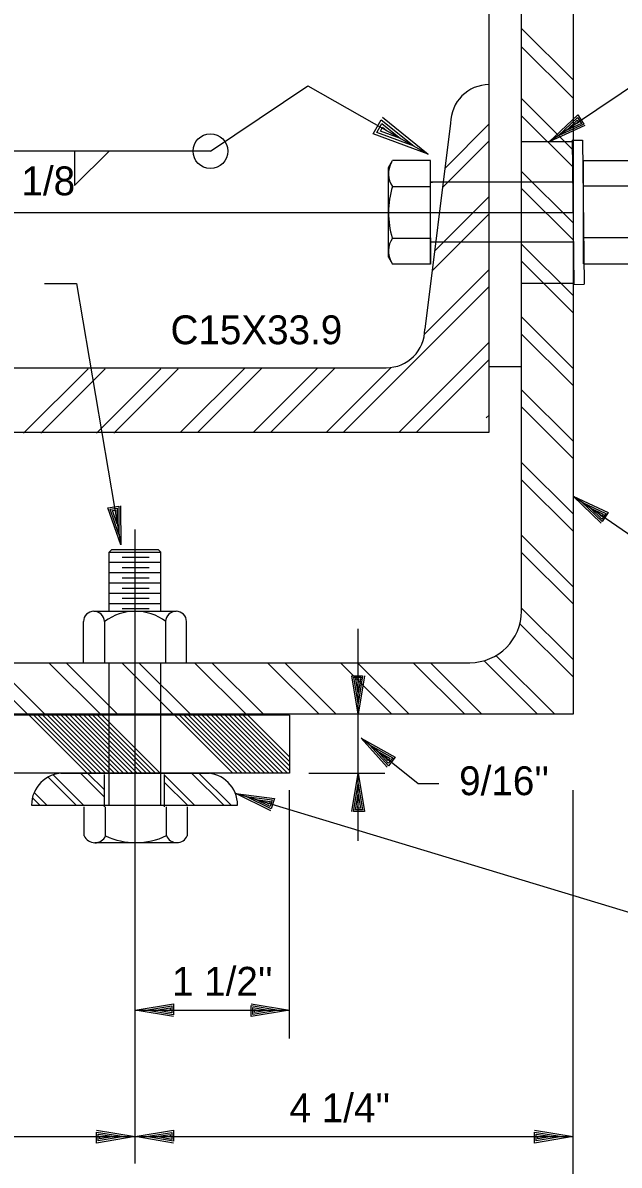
# Model space of a CAD drawing. Extents: x 0.1 to 13.5, y 0.1 to 9.5.
# Drawn here: x 5.352 to 6.316, y 1.255 to 3.105 of the extents above; entities that cross this region are included whole.
import ezdxf

# ---------------------------------------------------------------- set-up
doc = ezdxf.new("R2010")
doc.units = 0
for name, color, linetype in [('Level 1', 7, 'Continuous'), ('Level 10', 7, 'Continuous'), ('Level 13', 7, 'Continuous'), ('Level 2', 7, 'Continuous'), ('Level 25', 7, 'Continuous'), ('Level 3', 7, 'Continuous'), ('Level 36', 7, 'Continuous'), ('Level 50', 7, 'Continuous')]:
    doc.layers.add(name, color=color, linetype=linetype)

msp = doc.modelspace()

# ---------------------------------------------------------------- linework, layer by layer
at = {"layer": 'Level 1'}
msp.add_line((5.4129, 1.8899), (5.6536, 1.8899), dxfattribs=at)
for centre, start, end in [((5.4178, 1.8378), 90, 180), ((5.6469, 1.8378), 0, 90)]:
    msp.add_arc(centre, 0.0521, start, end, dxfattribs=at)
at = {"layer": 'Level 10'}
for p, q in [((5.4496, 1.8378), (5.4005, 1.8869)), ((5.4839, 1.8507), (5.4447, 1.8899)), ((5.4839, 1.8625), (5.4564, 1.8899)), ((5.6295, 1.8378), (5.5809, 1.8864)), ((5.6767, 1.8378), (5.6246, 1.8899)), ((5.6884, 1.8378), (5.6364, 1.8899)), ((5.4378, 1.8378), (5.3924, 1.8833)), ((5.6177, 1.8378), (5.5809, 1.8747)), ((5.3789, 1.8378), (5.3671, 1.8497)), ((5.3907, 1.8378), (5.37, 1.8585))]:
    msp.add_line(p, q, dxfattribs=at)
at = {"layer": 'Level 13'}
for p, q in [((6.2403, 2.9144), (6.257, 2.9145)), ((6.2403, 2.9144), (6.2426, 2.681)), ((6.257, 2.9145), (6.2593, 2.6812)), ((5.9431, 2.8702), (5.9496, 2.8814)), ((5.9431, 2.7252), (5.9431, 2.8702)), ((6.011, 2.8814), (5.9496, 2.8814)), ((6.011, 2.7139), (6.011, 2.8814)), ((6.2585, 2.7145), (6.2585, 2.8819)), ((6.2585, 2.8819), (6.338, 2.8819)), ((5.9494, 2.8397), (6.011, 2.8397)), ((6.2414, 2.8467), (6.011, 2.8467)), ((6.014, 2.8462), (6.011, 2.8462)), ((6.3382, 2.8402), (6.2585, 2.8402)), ((5.9494, 2.7557), (6.011, 2.7557)), ((6.011, 2.7563), (6.011, 2.7139)), ((6.3382, 2.7563), (6.2585, 2.7563)), ((6.2414, 2.7497), (6.011, 2.7497)), ((6.014, 2.7492), (6.011, 2.7492)), ((5.9431, 2.7252), (5.9496, 2.7139)), ((6.011, 2.7139), (5.9496, 2.7139)), ((6.2585, 2.7145), (6.338, 2.7145)), ((6.2426, 2.681), (6.2593, 2.6812)), ((5.4914, 2.2476), (5.4958, 2.2519)), ((5.4914, 2.2478), (5.5747, 2.2478)), ((5.4914, 2.1518), (5.4914, 2.2476)), ((5.4958, 2.2519), (5.5705, 2.2519)), ((5.5123, 2.2395), (5.5559, 2.2395)), ((5.5747, 2.2473), (5.5705, 2.2519)), ((5.5747, 2.1518), (5.5747, 2.2473)), ((5.4914, 2.2311), (5.5747, 2.2311)), ((5.5123, 2.2228), (5.5559, 2.2228)), ((5.4914, 2.2145), (5.5747, 2.2145)), ((5.5123, 2.2061), (5.5559, 2.2061)), ((5.4914, 2.1978), (5.5747, 2.1978)), ((5.5123, 2.1895), (5.5559, 2.1895)), ((5.4914, 2.1811), (5.5747, 2.1811)), ((5.4914, 2.1645), (5.5747, 2.1645)), ((5.5123, 2.1728), (5.5559, 2.1728)), ((5.4667, 2.1518), (5.5996, 2.1518)), ((5.5123, 2.1561), (5.5559, 2.1561)), ((5.4497, 2.0686), (5.4497, 2.1351)), ((5.4842, 2.0686), (5.4842, 2.1351)), ((5.5827, 2.0686), (5.5827, 2.1351)), ((5.6164, 2.0686), (5.6164, 2.1351)), ((5.7831, 1.9837), (4.8892, 1.9837)), ((5.362, 1.9837), (5.4557, 1.8899)), ((5.3694, 1.9837), (5.4631, 1.8899)), ((5.3767, 1.9837), (5.4705, 1.8899)), ((5.3841, 1.9837), (5.4779, 1.8899)), ((5.3914, 1.9837), (5.4852, 1.8899)), ((5.3988, 1.9837), (5.4926, 1.8899)), ((5.4062, 1.9837), (5.4999, 1.8899)), ((5.4136, 1.9837), (5.5073, 1.8899)), ((5.4209, 1.9837), (5.5147, 1.8899)), ((5.4283, 1.9837), (5.522, 1.8899)), ((5.4357, 1.9837), (5.5294, 1.8899)), ((5.443, 1.9837), (5.5368, 1.8899)), ((5.4504, 1.9837), (5.5441, 1.8899)), ((5.4577, 1.9837), (5.5515, 1.8899)), ((5.4651, 1.9837), (5.5589, 1.8899)), ((5.4725, 1.9837), (5.5662, 1.8899)), ((5.4798, 1.9837), (5.5736, 1.8899)), ((5.5977, 1.9837), (5.6914, 1.8899)), ((5.605, 1.9837), (5.6988, 1.8899)), ((5.6124, 1.9837), (5.7062, 1.8899)), ((5.6197, 1.9837), (5.7135, 1.8899)), ((5.6271, 1.9837), (5.7209, 1.8899)), ((5.6345, 1.9837), (5.7282, 1.8899)), ((5.6419, 1.9837), (5.7356, 1.8899)), ((5.6492, 1.9837), (5.7429, 1.8899)), ((5.6566, 1.9837), (5.7503, 1.8899)), ((5.6639, 1.9837), (5.7577, 1.8899)), ((5.6713, 1.9837), (5.7651, 1.8899)), ((5.6787, 1.9837), (5.7724, 1.8899)), ((5.686, 1.9837), (5.7798, 1.8899)), ((5.6934, 1.9837), (5.7831, 1.894)), ((5.7008, 1.9837), (5.7831, 1.9014)), ((5.7082, 1.9837), (5.7831, 1.9087)), ((5.7155, 1.9837), (5.7831, 1.9161)), ((5.7831, 1.9837), (5.7831, 1.8899)), ((5.7831, 1.8899), (5.0871, 1.8899)), ((5.451, 1.8899), (5.6177, 1.8899)), ((5.451, 1.7884), (5.451, 1.8354)), ((5.4854, 1.788), (5.4854, 1.8354)), ((5.584, 1.7882), (5.584, 1.8354)), ((5.6177, 1.7884), (5.6177, 1.8354)), ((5.468, 1.7772), (5.6009, 1.7772))]:
    msp.add_line(p, q, dxfattribs=at)
for centre, radius, start, end in [((5.9794, 2.8602), 0.0364, 149.7124, 214.511), ((6.0886, 2.7972), 0.1455, 163.0184, 196.4966), ((5.9794, 2.7352), 0.0364, 145.489, 210.2876), ((5.4666, 2.1349), 0.0169, 0.5658, 179.4341), ((5.5334, 2.0707), 0.0812, 52.4343, 127.5657), ((5.5995, 2.1349), 0.0169, 0.4975, 179.5025), ((5.4682, 1.7958), 0.0188, 203.1675, 335.9991), ((5.5343, 1.891), 0.1138, 244.5519, 295.884), ((5.6008, 1.7955), 0.0182, 202.375, 337.1995)]:
    msp.add_arc(centre, radius, start, end, dxfattribs=at)
at = {"layer": 'Level 2'}
for p, q in [((5.4914, 1.8378), (5.4914, 2.0686)), ((5.5747, 1.8378), (5.5747, 2.0686)), ((5.4839, 1.8354), (5.4839, 1.8875)), ((5.5809, 1.8354), (5.5809, 1.8875)), ((5.3657, 1.8378), (5.699, 1.8378))]:
    msp.add_line(p, q, dxfattribs=at)
at = {"layer": 'Level 25'}
for p, q in [((6.106, 3.0045), (6.106, 3.8691)), ((6.1581, 2.5481), (6.1581, 3.8692)), ((6.2414, 3.0122), (6.1581, 3.0956)), ((6.2414, 2.9825), (6.1581, 3.0658)), ((5.655, 2.8968), (5.8125, 3.0026)), ((5.8125, 3.0026), (6.0069, 2.8918)), ((6.2414, 2.8986), (6.1581, 2.9819)), ((6.0435, 2.942), (6.0018, 2.6086)), ((6.106, 2.9411), (6.0345, 2.8695)), ((6.2414, 2.8708), (6.1581, 2.9542)), ((5.9843, 2.9047), (5.9843, 2.9047)), ((6.106, 2.9133), (6.0305, 2.8377)), ((6.1581, 2.9123), (6.2414, 2.9123)), ((5.655, 2.8968), (5.2799, 2.8968)), ((5.4354, 2.8973), (5.4354, 2.8411)), ((5.4354, 2.8411), (5.4912, 2.897)), ((6.0069, 2.8918), (6.0069, 2.8918)), ((6.2414, 2.7807), (6.1581, 2.8641)), ((6.2414, 2.753), (6.1581, 2.8363)), ((6.106, 2.8232), (6.0176, 2.7348)), ((4.486, 2.7977), (6.2414, 2.7977)), ((6.106, 2.7954), (6.0136, 2.7031)), ((6.2414, 2.6629), (6.1581, 2.7462)), ((6.106, 2.7053), (6.0008, 2.6001)), ((6.2414, 2.6351), (6.1581, 2.7185)), ((6.1581, 2.6831), (6.2414, 2.6831)), ((6.106, 2.6776), (5.8704, 2.442)), ((6.2414, 2.545), (6.1581, 2.6284)), ((6.2414, 2.5173), (6.1581, 2.6006)), ((6.106, 2.5875), (5.9605, 2.442)), ((6.106, 2.5597), (5.9883, 2.442)), ((4.6416, 2.5461), (5.9393, 2.5461)), ((5.4572, 2.5446), (5.353, 2.4404)), ((5.485, 2.5446), (5.3808, 2.4404)), ((5.5751, 2.5446), (5.4709, 2.4404)), ((5.6028, 2.5446), (5.4987, 2.4404)), ((5.7111, 2.5461), (5.6069, 2.442)), ((5.7389, 2.5461), (5.6347, 2.442)), ((5.829, 2.5461), (5.7248, 2.442)), ((5.8568, 2.5461), (5.7526, 2.442)), ((5.9468, 2.5461), (5.8426, 2.442)), ((6.106, 2.5481), (6.1581, 2.5481)), ((6.2414, 2.4272), (6.1581, 2.5106)), ((6.2414, 2.3994), (6.1581, 2.4827)), ((6.106, 2.4696), (6.1012, 2.4648)), ((4.6416, 2.442), (6.106, 2.442)), ((6.2414, 2.3094), (6.1581, 2.3927)), ((6.2414, 2.2816), (6.1581, 2.3649)), ((5.5331, 1.8899), (5.5331, 2.2841)), ((6.2414, 2.1915), (6.1581, 2.2748)), ((6.2414, 2.1637), (6.1581, 2.2471)), ((6.2414, 2.0737), (6.1581, 2.157)), ((6.2414, 2.0459), (6.155, 2.1323)), ((5.8938, 1.9852), (5.8938, 2.1233)), ((6.1842, 1.9852), (6.0976, 2.0718)), ((6.212, 1.9852), (6.1168, 2.0804)), ((5.3593, 1.9852), (5.286, 2.0584)), ((5.387, 1.9852), (5.3064, 2.0659)), ((5.4771, 1.9852), (5.3938, 2.0686)), ((5.5049, 1.9852), (5.4216, 2.0686)), ((5.5949, 1.9852), (5.5116, 2.0686)), ((5.6227, 1.9852), (5.5394, 2.0686)), ((5.7128, 1.9852), (5.6295, 2.0686)), ((5.7406, 1.9852), (5.6573, 2.0686)), ((5.8307, 1.9852), (5.7473, 2.0686)), ((5.8584, 1.9852), (5.7751, 2.0686)), ((5.9485, 1.9852), (5.8652, 2.0686)), ((5.9763, 1.9852), (5.8929, 2.0685)), ((6.0664, 1.9852), (5.983, 2.0686)), ((6.0942, 1.9852), (6.0108, 2.0686)), ((5.8938, 1.8899), (5.8938, 1.9852)), ((5.5331, 1.2576), (5.5331, 1.8899)), ((5.8144, 1.8899), (5.9373, 1.8899)), ((5.8938, 1.7801), (5.8938, 1.8899)), ((5.7831, 1.46), (5.7831, 1.862)), ((6.2414, 1.0579), (6.2414, 1.862)), ((5.5331, 1.5061), (5.7831, 1.5061)), ((4.8872, 1.3012), (5.5331, 1.3012)), ((5.5331, 1.3012), (6.2414, 1.3012))]:
    msp.add_line(p, q, dxfattribs=at)
msp.add_lwpolyline([(5.9333, 2.9516), (6.0069, 2.8918), (5.918, 2.9247), (5.9311, 2.9477), (5.9843, 2.9047), (5.9239, 2.927), (5.9323, 2.9418), (5.9626, 2.9171), (5.9299, 2.9294), (5.9333, 2.9355), (5.94, 2.93)], dxfattribs=at)
msp.add_circle((5.655, 2.8968), 0.0281, dxfattribs=at)
for centre, start, end in [((6.106, 2.942), 90, 180), ((5.9393, 2.6086), 270, 0)]:
    msp.add_arc(centre, 0.0625, start, end, dxfattribs=at)
at = {"layer": 'Level 3'}
for p, q in [((6.2029, 2.9121), (6.2029, 2.9121)), ((6.2173, 2.9217), (6.2173, 2.9217)), ((6.2414, 2.3384), (6.2414, 2.3384)), ((6.2556, 2.3286), (6.2556, 2.3286)), ((5.507, 2.2764), (5.507, 2.2764)), ((5.5099, 2.2593), (5.5099, 2.2593)), ((5.8938, 1.9852), (5.8938, 1.9852)), ((5.8989, 1.9466), (5.8989, 1.9466)), ((5.9124, 1.9357), (5.9124, 1.9357)), ((5.8938, 1.8899), (5.8938, 1.8899)), ((5.696, 1.8569), (5.696, 1.8569)), ((5.7126, 1.8519), (5.7126, 1.8519)), ((5.5331, 1.3012), (5.5331, 1.3012))]:
    msp.add_line(p, q, dxfattribs=at)
for points in [[(6.5819, 3.0683), (6.4359, 3.0683), (6.2029, 2.9121)], [(6.2605, 2.9382), (6.2029, 2.9121), (6.249, 2.9554), (6.2588, 2.9407), (6.2173, 2.9217), (6.2486, 2.9511), (6.2549, 2.9417), (6.2312, 2.931), (6.2483, 2.9469), (6.2508, 2.943), (6.2456, 2.9407)], [(5.3868, 2.6826), (5.4385, 2.6826), (5.5099, 2.2593)], [(6.587, 2.1566), (6.5051, 2.1566), (6.2414, 2.3384)], [(6.2868, 2.2945), (6.2414, 2.3384), (6.2985, 2.3115), (6.2885, 2.297), (6.2556, 2.3286), (6.2944, 2.3103), (6.288, 2.301), (6.2693, 2.3191), (6.2904, 2.3091), (6.2877, 2.3052), (6.2836, 2.3093)], [(5.5097, 2.3225), (5.5099, 2.2593), (5.4893, 2.3191), (5.5067, 2.322), (5.507, 2.2764), (5.493, 2.317), (5.5042, 2.3189), (5.5042, 2.2928), (5.4968, 2.3149), (5.5014, 2.3157), (5.5013, 2.3099)], [(6.0244, 1.8723), (5.9911, 1.8723), (5.8989, 1.9466)], [(5.941, 1.8994), (5.8989, 1.9466), (5.9539, 1.9155), (5.9428, 1.9017), (5.9124, 1.9357), (5.9498, 1.9146), (5.9426, 1.9058), (5.9254, 1.9252), (5.9456, 1.9137), (5.9427, 1.91), (5.9389, 1.9144)], [(6.5972, 1.6546), (6.3643, 1.6546), (5.696, 1.8569)], [(5.7527, 1.829), (5.696, 1.8569), (5.7587, 1.8488), (5.7535, 1.8318), (5.7126, 1.8519), (5.7551, 1.8463), (5.7519, 1.8355), (5.7286, 1.8471), (5.7516, 1.8439), (5.7503, 1.8394), (5.7451, 1.8421)]]:
    msp.add_lwpolyline(points, dxfattribs=at)
at = {"layer": 'Level 36'}
for p, q in [((6.2414, 3.3185), (6.2414, 1.9852)), ((6.1581, 2.1519), (6.1581, 3.2357)), ((6.106, 2.442), (6.106, 3.0045)), ((5.3247, 2.0686), (6.0747, 2.0686)), ((6.2414, 1.9852), (5.2414, 1.9852))]:
    msp.add_line(p, q, dxfattribs=at)
msp.add_arc((6.0747, 2.1519), 0.0833, 270, 0, dxfattribs=at)
at = {"layer": 'Level 50'}
for p, q in [((5.8938, 2.0025), (5.8938, 2.0025)), ((5.8938, 1.9852), (5.8938, 1.9852)), ((5.8938, 1.8899), (5.8938, 1.8899)), ((5.8938, 1.8726), (5.8938, 1.8726)), ((5.5331, 1.5061), (5.5331, 1.5061)), ((5.5504, 1.5061), (5.5504, 1.5061)), ((5.7657, 1.5061), (5.7657, 1.5061)), ((5.7831, 1.5061), (5.7831, 1.5061)), ((5.5157, 1.3012), (5.5157, 1.3012)), ((5.5331, 1.3012), (5.5331, 1.3012)), ((5.5331, 1.3012), (5.5331, 1.3012)), ((5.5504, 1.3012), (5.5504, 1.3012)), ((6.2241, 1.3012), (6.2241, 1.3012)), ((6.2414, 1.3012), (6.2414, 1.3012))]:
    msp.add_line(p, q, dxfattribs=at)
for points in [[(5.9041, 2.0475), (5.8938, 1.9852), (5.8835, 2.0475), (5.9011, 2.0475), (5.8938, 2.0025), (5.8868, 2.0449), (5.8981, 2.0449), (5.8938, 2.0192), (5.8901, 2.0422), (5.8948, 2.0422), (5.8938, 2.0365)], [(5.8835, 1.8276), (5.8938, 1.8899), (5.9041, 1.8276), (5.8865, 1.8276), (5.8938, 1.8726), (5.9008, 1.8302), (5.8895, 1.8302), (5.8938, 1.8559), (5.8975, 1.8329), (5.8928, 1.8329), (5.8938, 1.8386)], [(5.5954, 1.4957), (5.5331, 1.5061), (5.5954, 1.5164), (5.5954, 1.4987), (5.5504, 1.5061), (5.5927, 1.5131), (5.5927, 1.5017), (5.5671, 1.5061), (5.5901, 1.5097), (5.5901, 1.5051), (5.5844, 1.5061)], [(5.7207, 1.5164), (5.7831, 1.5061), (5.7207, 1.4957), (5.7207, 1.5134), (5.7657, 1.5061), (5.7234, 1.4991), (5.7234, 1.5104), (5.7491, 1.5061), (5.7261, 1.5024), (5.7261, 1.5071), (5.7317, 1.5061)], [(5.4707, 1.3115), (5.5331, 1.3012), (5.4707, 1.2908), (5.4707, 1.3085), (5.5157, 1.3012), (5.4734, 1.2942), (5.4734, 1.3055), (5.4991, 1.3012), (5.4761, 1.2975), (5.4761, 1.3022), (5.4817, 1.3012)], [(5.5954, 1.2908), (5.5331, 1.3012), (5.5954, 1.3115), (5.5954, 1.2938), (5.5504, 1.3012), (5.5927, 1.3082), (5.5927, 1.2968), (5.5671, 1.3012), (5.5901, 1.3048), (5.5901, 1.3002), (5.5844, 1.3012)], [(6.1791, 1.3115), (6.2414, 1.3012), (6.1791, 1.2908), (6.1791, 1.3085), (6.2241, 1.3012), (6.1817, 1.2942), (6.1817, 1.3055), (6.2074, 1.3012), (6.1844, 1.2975), (6.1844, 1.3022), (6.1901, 1.3012)]]:
    msp.add_lwpolyline(points, dxfattribs=at)

# ---------------------------------------------------------------- texts
at = {"layer": 'Level 25'}
msp.add_text('C15X33.9', height=0.0467, dxfattribs=at).set_placement((5.5905, 2.5842))
at = {"layer": 'Level 3'}
for s, p in [('1/8', (5.3494, 2.8253)), ("9/16''", (6.0573, 1.8541)), ("1 1/2''", (5.5929, 1.5294)), ("4 1/4''", (5.783, 1.3245))]:
    msp.add_text(s, height=0.0467, dxfattribs=at).set_placement(p)

doc.saveas('drawing.dxf')
